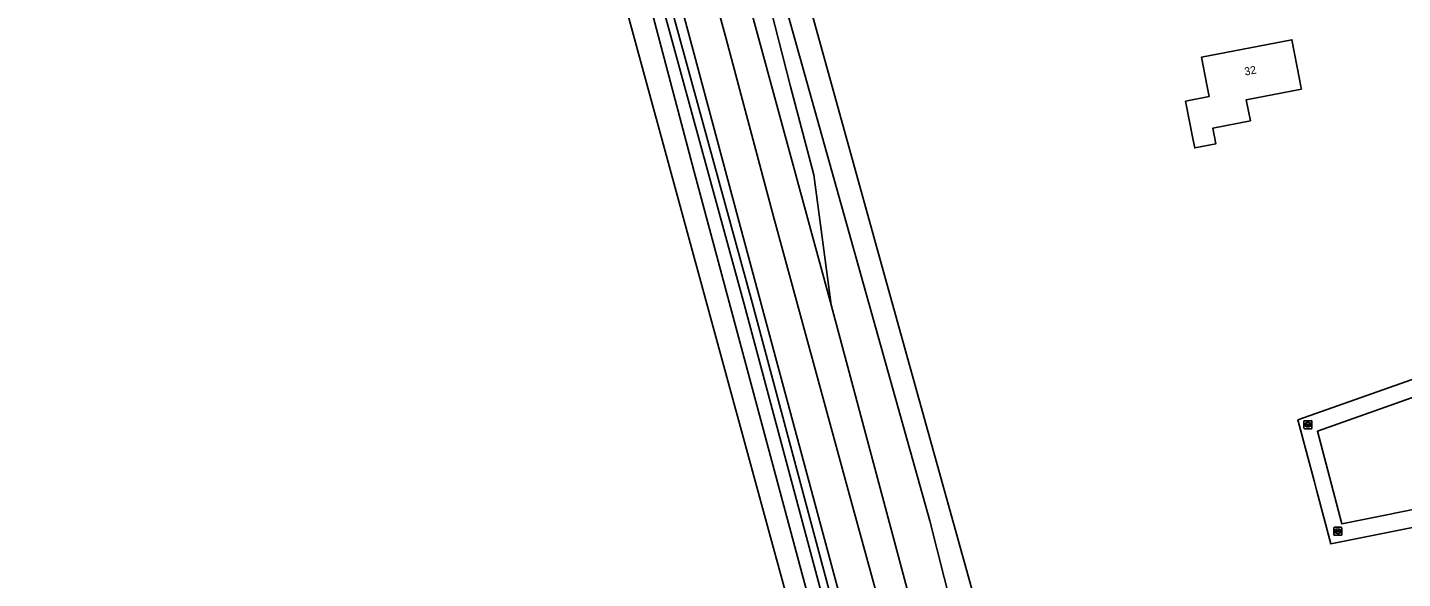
# Model space of a CAD drawing. Extents: x 162661 to 163484, y 380247 to 381230.
# Drawn here: x 162686.4 to 162858.2, y 380438.6 to 380507.4 of the extents above; entities that cross this region are included whole.
import ezdxf

# ---------------------------------------------------------------- set-up
doc = ezdxf.new("R2010")
doc.units = 0
for name, color, linetype in [('IMGEO_Berm_groen', 7, 'Continuous'), ('IMGEO_Erf', 7, 'Continuous'), ('IMGEO_Groenvoorziening', 7, 'Continuous'), ('IMGEO_Haag', 7, 'Continuous'), ('IMGEO_Pand', 7, 'Continuous'), ('IMGEO_Pand_nummerreeks', 7, 'Continuous'), ('IMGEO_Rijbaan_regionaal_gesloten', 7, 'Continuous'), ('IMGEO_Rioolput', 7, 'Continuous'), ('IMGEO_Voetpad_open', 7, 'Continuous'), ('IMGEO_Waterloop', 7, 'Continuous')]:
    doc.layers.add(name, color=color, linetype=linetype)

msp = doc.modelspace()

# ---------------------------------------------------------------- linework, layer by layer
at = {"layer": 'IMGEO_Berm_groen'}
for points in [[(162835.05, 380247), (162836.57, 380247.15), (162835.89, 380249.78), (162833.28, 380258.46), (162775.95, 380472.81), (162761.49, 380525.66), (162756.47, 380544.53), (162753.07, 380555.96), (162748.05, 380572.5), (162742.44, 380591.57), (162738.84, 380602.55), (162737.33, 380602.13), (162737.83, 380600.63), (162739, 380597.5), (162757.61, 380535.1), (162769.66, 380489.54), (162783.2, 380439.1), (162797.9, 380384.66), (162817.04, 380314.25), (162824.68, 380286.95), (162831.58, 380259.82)], [(162837.58, 380247.25), (162838.74, 380247.37), (162837.11, 380253.58), (162829.67, 380281.14), (162816.39, 380330.35), (162801.02, 380387.8), (162791.82, 380421.83), (162775.32, 380483.08), (162767.37, 380512.8), (162751.61, 380569.11), (162741.09, 380603.18), (162739.8, 380602.82), (162743.39, 380591.86), (162749.01, 380572.79), (162754.02, 380556.25), (162757.44, 380544.8), (162762.45, 380525.92), (162776.92, 380473.04), (162834.27, 380258.61), (162836.86, 380250.04)], [(162847.08, 380248.2), (162851.52, 380248.65), (162851.46, 380248.89), (162848.33, 380260.66), (162828.31, 380335.86), (162817.91, 380373.89), (162806.35, 380417.28), (162799.14, 380445.75), (162790.57, 380476.35), (162780.44, 380512.49), (162774.17, 380538.45), (162772.03, 380537.84), (162772.87, 380534.8), (162781.71, 380500), (162784.65, 380488.97), (162786.79, 380472.74), (162798.38, 380429.43), (162813.46, 380372.95), (162817.4, 380358.11), (162827.48, 380320.82), (162837.33, 380284.65), (162844.77, 380256.65)]]:
    msp.add_lwpolyline(points, close=True, dxfattribs=at)
at = {"layer": 'IMGEO_Erf'}
for points in [[(162747.47, 380643.78), (162754.58, 380617.79), (162767.63, 380570.63), (162781.76, 380518.45), (162783.54, 380512.22), (162793.32, 380477.02), (162808.83, 380421.22), (162810.28, 380415.59), (162897.43, 380433.04)], [(162890.42, 380451.12), (162849.23, 380442.9), (162847.5, 380449.46), (162847.16, 380450.75), (162845.14, 380458.39), (162883.5, 380471.92)]]:
    msp.add_lwpolyline(points, dxfattribs=at)
msp.add_lwpolyline([(162834.04, 380498.75), (162833.79, 380500), (162833.08, 380503.66), (162844.37, 380505.85), (162845.32, 380500.94), (162845.51, 380500), (162845.56, 380499.7), (162838.68, 380498.35), (162839.19, 380495.74), (162834.51, 380494.83), (162834.89, 380492.87), (162832.23, 380492.35), (162832.04, 380493.32), (162831.09, 380498.18)], close=True, dxfattribs=at)
at = {"layer": 'IMGEO_Groenvoorziening'}
for points in [[(162836.57, 380247.15), (162837.58, 380247.25), (162836.86, 380250.04), (162834.27, 380258.61), (162776.92, 380473.04), (162762.45, 380525.92), (162757.44, 380544.8), (162754.02, 380556.25), (162749.01, 380572.79), (162743.39, 380591.86), (162739.8, 380602.82), (162738.84, 380602.55), (162742.44, 380591.57), (162748.05, 380572.5), (162753.07, 380555.96), (162756.47, 380544.53), (162761.49, 380525.66), (162775.95, 380472.81), (162833.28, 380258.46), (162835.89, 380249.78)], [(162889.79, 380454.74), (162885.93, 380468.84), (162885.54, 380470.29), (162882.68, 380469.41), (162847.56, 380456.96), (162850.61, 380445.39), (162888.39, 380452.95), (162889.84, 380453.21), (162889.45, 380454.64)]]:
    msp.add_lwpolyline(points, close=True, dxfattribs=at)
at = {"layer": 'IMGEO_Haag'}
msp.add_lwpolyline([(162836.57, 380247.15), (162837.58, 380247.25), (162836.86, 380250.04), (162834.27, 380258.61), (162776.92, 380473.04), (162762.45, 380525.92), (162757.44, 380544.8), (162754.02, 380556.25), (162749.01, 380572.79), (162743.39, 380591.86), (162739.8, 380602.82), (162738.84, 380602.55), (162742.44, 380591.57), (162748.05, 380572.5), (162753.07, 380555.96), (162756.47, 380544.53), (162761.49, 380525.66), (162775.95, 380472.81), (162833.28, 380258.46), (162835.89, 380249.78)], close=True, dxfattribs=at)
at = {"layer": 'IMGEO_Pand'}
msp.add_lwpolyline([(162832.04, 380493.32), (162832.23, 380492.35), (162834.89, 380492.87), (162834.51, 380494.83), (162839.19, 380495.74), (162838.68, 380498.35), (162845.56, 380499.7), (162845.51, 380500), (162845.32, 380500.94), (162844.37, 380505.85), (162833.08, 380503.66), (162833.79, 380500), (162834.04, 380498.75), (162831.09, 380498.18)], close=True, dxfattribs=at)
at = {"layer": 'IMGEO_Rijbaan_regionaal_gesloten'}
for points in [[(162686.38, 380740.14), (162737.06, 380598.14), (162832.98, 380246.79), (162835.05, 380247), (162831.58, 380259.82), (162824.68, 380286.95), (162817.04, 380314.25), (162797.9, 380384.66), (162783.2, 380439.1), (162769.66, 380489.54), (162757.61, 380535.1), (162739, 380597.5), (162737.83, 380600.63), (162737.33, 380602.13), (162726.89, 380632.73)], [(162726.18, 380646.81), (162735.43, 380620.82), (162741.09, 380603.18), (162751.61, 380569.11), (162767.37, 380512.8), (162775.32, 380483.08), (162791.82, 380421.83)], [(162798.38, 380429.43), (162786.79, 380472.74), (162774.38, 380518.38), (162760.22, 380568.65), (162756.51, 380580.9), (162751.88, 380596.19), (162747.48, 380610.72), (162743.33, 380622.78), (162738.46, 380636.84)], [(162735.76, 380632.97), (162743.65, 380609.98), (162746.99, 380598.08), (162753.96, 380575.32), (162758.34, 380561.08), (162767.16, 380529.98), (162773.68, 380505.98), (162779.6, 380483.79), (162788.92, 380449.59), (162795.45, 380425.78)], [(162795.45, 380425.78), (162788.92, 380449.59), (162779.6, 380483.79), (162773.68, 380505.98), (162767.16, 380529.98), (162758.34, 380561.08), (162753.96, 380575.32), (162746.99, 380598.08), (162743.65, 380609.98), (162735.76, 380632.97)], [(162766.17, 380555.67), (162762.54, 380563.42), (162760.22, 380568.65), (162774.38, 380518.38), (162786.79, 380472.74), (162784.65, 380488.97), (162781.71, 380500), (162772.87, 380534.8)]]:
    msp.add_lwpolyline(points, dxfattribs=at)
at = {"layer": 'IMGEO_Rioolput'}
for p, q in [((162845.88, 380457.34), (162845.88, 380458.2)), ((162845.95, 380458.27), (162846.8, 380458.27)), ((162846.18, 380457.81), (162846.58, 380457.81)), ((162846.37, 380458.05), (162846.39, 380458.05)), ((162846.88, 380458.2), (162846.88, 380457.34)), ((162846.8, 380457.27), (162845.95, 380457.27)), ((162846.14, 380457.76), (162846.14, 380457.78)), ((162846.57, 380457.73), (162846.18, 380457.73)), ((162846.39, 380457.49), (162846.36, 380457.49)), ((162846.62, 380457.78), (162846.62, 380457.76)), ((162849.62, 380444.04), (162849.62, 380444.89)), ((162849.69, 380444.97), (162850.55, 380444.97)), ((162849.88, 380444.46), (162849.88, 380444.47)), ((162849.92, 380444.51), (162850.32, 380444.51)), ((162850.32, 380444.42), (162849.92, 380444.42)), ((162850.13, 380444.19), (162850.1, 380444.19)), ((162850.11, 380444.75), (162850.13, 380444.75)), ((162850.36, 380444.47), (162850.36, 380444.46)), ((162850.62, 380444.89), (162850.62, 380444.04)), ((162850.55, 380443.97), (162849.69, 380443.97))]:
    msp.add_line(p, q, dxfattribs=at)
for points in [[(162845.88, 380457.34), (162845.88, 380458.2)], [(162845.95, 380458.27), (162846.8, 380458.27)], [(162846.88, 380458.2), (162846.88, 380457.34)], [(162846.8, 380457.27), (162845.95, 380457.27)], [(162849.62, 380444.04), (162849.62, 380444.89)], [(162849.69, 380444.97), (162850.55, 380444.97)], [(162850.62, 380444.89), (162850.62, 380444.04)], [(162850.55, 380443.97), (162849.69, 380443.97)]]:
    msp.add_lwpolyline(points, dxfattribs=at)
for centre, radius, start, end in [((162845.95, 380458.2), 0.0765, 91.552, 178.448), ((162845.95, 380458.2), 0.0765, 91.552, 178.448), ((162846.18, 380457.77), 0.0403, 85.8775, 175.7526), ((162846.58, 380457.78), 0.0386, 1.7309, 96.639), ((162846.8, 380458.2), 0.0765, 1.552, 88.448), ((162846.8, 380458.2), 0.0765, 1.552, 88.448), ((162845.95, 380457.35), 0.0765, 181.552, 268.448), ((162845.95, 380457.35), 0.0765, 181.552, 268.448), ((162846.17, 380457.76), 0.0366, 178.938, 274.7102), ((162846.58, 380457.77), 0.043, 264.8664, 352.4533), ((162846.8, 380457.35), 0.0765, 271.552, 358.448), ((162846.8, 380457.35), 0.0765, 271.552, 358.448), ((162849.7, 380444.89), 0.0765, 91.552, 178.448), ((162849.7, 380444.89), 0.0765, 91.552, 178.448), ((162849.92, 380444.47), 0.0403, 85.8775, 175.7526), ((162849.91, 380444.46), 0.0366, 178.938, 274.7102), ((162850.32, 380444.47), 0.0386, 1.7309, 96.639), ((162850.32, 380444.47), 0.043, 264.8664, 352.4533), ((162850.54, 380444.89), 0.0765, 1.552, 88.448), ((162850.54, 380444.89), 0.0765, 1.552, 88.448), ((162849.7, 380444.04), 0.0765, 181.552, 268.448), ((162849.7, 380444.04), 0.0765, 181.552, 268.448), ((162850.54, 380444.04), 0.0765, 271.552, 358.448), ((162850.54, 380444.04), 0.0765, 271.552, 358.448)]:
    msp.add_arc(centre, radius, start, end, dxfattribs=at)
for centre, major_axis, ratio, start_param, end_param in [((162846.36, 380457.77), (-0.387, 0.002), 0.722429, 4.712389, 7.853982), ((162846.39, 380457.77), (-0.39, 0.002), 0.717154, 1.570796, 4.712389), ((162850.11, 380444.47), (-0.387, 0.002), 0.722429, 4.712389, 7.853982), ((162850.13, 380444.47), (-0.39, 0.002), 0.717154, 1.570796, 4.712389)]:
    msp.add_ellipse(centre, major_axis=major_axis, ratio=ratio, start_param=start_param, end_param=end_param, dxfattribs=at)
at = {"layer": 'IMGEO_Voetpad_open'}
msp.add_lwpolyline([(162884.98, 380472.33), (162883.5, 380471.92), (162845.14, 380458.39), (162847.16, 380450.75), (162847.5, 380449.46), (162849.23, 380442.9), (162890.42, 380451.12), (162889.84, 380453.21), (162888.39, 380452.95), (162850.61, 380445.39), (162847.56, 380456.96), (162882.68, 380469.41), (162885.54, 380470.29)], close=True, dxfattribs=at)
at = {"layer": 'IMGEO_Waterloop'}
for points in [[(162732.55, 380692.05), (162772.78, 380543.61), (162772.93, 380543.05), (162774.08, 380538.77), (162774.17, 380538.45), (162780.44, 380512.49), (162790.57, 380476.35), (162799.14, 380445.75), (162806.35, 380417.28), (162817.91, 380373.89), (162828.31, 380335.86), (162848.33, 380260.66), (162851.46, 380248.89), (162851.52, 380248.65), (162854.54, 380248.95)], [(162857.66, 380356.8), (162855.7, 380356.69), (162846.46, 380354.52), (162841.85, 380353.11), (162827.56, 380349.18), (162824.18, 380361.77), (162810.28, 380415.59), (162808.83, 380421.22), (162793.32, 380477.02), (162783.54, 380512.22), (162781.76, 380518.45), (162767.63, 380570.63), (162754.58, 380617.79), (162747.47, 380643.78)]]:
    msp.add_lwpolyline(points, dxfattribs=at)

# ---------------------------------------------------------------- texts
at = {"layer": 'IMGEO_Pand_nummerreeks'}
msp.add_text('32', height=1, rotation=10.9875, dxfattribs=at).set_placement((162838.54, 380501.37))

doc.saveas('drawing.dxf')
